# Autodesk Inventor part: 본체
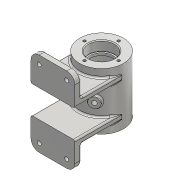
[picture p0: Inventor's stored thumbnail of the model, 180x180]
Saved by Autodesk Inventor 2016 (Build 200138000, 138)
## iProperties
Created: 2017-02
Part Number: 본체
Material: 알루미늄 6061
Document SubType Name: Modeling
Designer: H
Density: 2.7 g/cm^3
Appearance: 알루미늄 - 평지
Mass: 354.506 g
Surface Area: 423.347 cm^2
Volume: 131.299 cm^3
Author: H
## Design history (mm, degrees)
sketch "스케치1"
  geometry: L1 (0, 0)-(0, -48.036); L2 (0, 0)-(27, 0); L3 (27, 35)-(0, 35); L4 (0, 35)-(0, -35); L5 (0, -35)-(27, -35); L6 (27, -35)-(27, 35); L7 (0, -10)-(27, -10); L8 (32, -5)-(21.317, -5); L9 (21.317, -5)-(21.317, -10); L10 (21.317, -10)-(32, -10); L11 (32, -10)-(32, -5)
  constraints: 22 end point, 4 horizontal, 4 parallel, 4 point on line, 2 perpendicular, 1 vertical, 1 other
  dimensions: "d0" = 54 diameter of L6 L1; "d1" = 48.03642 distance of L1.start L1.end; "d2" = 27 distance of L1.start L2.end; "d4" = 70 distance of L5.end L3.start; "d5" = 5 distance of L10.end L8.start; "d6" = 10.68275 distance of L8.start L8.end; "d7" = 5 distance between parallel lines of L6 L11; "d109" = 25 distance between parallel lines of L5 L10
revolve "회전1" stored, may be unused: angle "d8" = 90 deg
revolve "회전2" stored, may be unused: angle "d9" = 90 deg
sketch "스케치2"
  geometry: L1 (-52, 52)-(-60, 52); L2 (-60, 52)-(-60, 17); L3 (-60, 17)-(-52, 17); L4 (-52, 17)-(-52, 52); L5 (0, 0)-(-22.662, 0); L6 (-52, 17)-(-2, 17); L7 (-2, 17)-(-2, 25); L8 (-2, 25)-(-52, 25); L9 (-52, 25)-(-52, 17)
  constraints: 18 end point, 4 parallel, 3 horizontal, 2 perpendicular
  dimensions: "d10" = 22.66207 distance of L5.start L5.end; "d11" = 52 distance between parallel lines of L5 L1; "d12" = 8 distance of L1.start L1.end; "d13" = 17 distance between parallel lines of L5 L3; "d14" = 60 distance from line of L5.start L2; "d15" = 50 distance of L7.end L8.end; "d16" = 8 distance of L6.end L7.end
extrude "돌출1" join sketch "스케치2" stored distance "d17" = 54; taper "d18" = 0 deg
sketch "스케치3"
  geometry: 2 further points
  constraints: 1 coincident
hole "구멍1" sketch "스케치3" at (0, 0) diameter "d19" = 32; stored, may be unused: countersink angle "d23" = 90 deg, drill point angle "d25" = 0 deg; dims "d20" = 6, "d21" = 4, "d22" = 2, "d24" = 12
sketch "스케치4"
  geometry: 2 further points
  constraints: 1 coincident
hole "구멍2" sketch "스케치4" at (0, 0) diameter "d26" = 28; stored, may be unused: countersink angle "d30" = 90 deg, drill point angle "d32" = 0 deg; dims "d27" = 6, "d28" = 4, "d29" = 2, "d31" = 3
sketch "스케치5"
  geometry: 2 further points
  constraints: 1 coincident
hole "구멍3" sketch "스케치5" at (0, 0) diameter "d33" = 44; stored, may be unused: countersink angle "d37" = 90 deg, drill point angle "d39" = 0 deg; dims "d34" = 6, "d35" = 4, "d36" = 2, "d38" = 40
sketch "스케치6"
  geometry: C1 r 5 at (0, 0) reference; 2 further points
  constraints: 1 coincident
hole "구멍4" sketch "스케치6" at (0, 0) diameter "d40" = 5.188; stored, may be unused: countersink angle "d44" = 90 deg, drill point angle "d46" = 0 deg; dims "d41" = 12, "d42" = 4, "d43" = 2, "d45" = 23.25
sketch "스케치8" dims "d47" = 9
  geometry: L1 (14.5, 14.402)-(10, 11.804); L2 (10, 11.804)-(5.5, 14.402); L3 (5.5, 14.402)-(5.5, 19.598); L4 (5.5, 19.598)-(10, 22.196); L5 (10, 22.196)-(14.5, 19.598); L6 (14.5, 19.598)-(14.5, 14.402); L7 (0, -8)-(0, 27) reference; 4 further points
  constraints: 12 end point, 1 coincident, 1 horizontal alignment, 1 midpoint, 1 parallel, 15 other
  dimensions: "d48" = 17 horizontal distance of point (10, 17) point (27, -25); "d49" = 42 vertical distance of point (27, -25) point (10, 17)
extrude "돌출2" cut sketch "스케치8" distance "d50" = 3; taper "d51" = 0 deg
sketch "스케치9"
  geometry: 2 further points
  dimensions: "d52" = 42 vertical distance of point (10, 17) point (27, -25); "d53" = 17 horizontal distance of point (27, -25) point (10, 17)
hole "구멍5" sketch "스케치9" at (10, 17) diameter "d54" = 5; stored, may be unused: countersink angle "d58" = 90 deg, drill point angle "d60" = 0 deg; dims "d55" = 12, "d56" = 4, "d57" = 2, "d59" = 23.25
sketch "스케치10"
  geometry: L1 (5, 32)-(-5, 32) reference; L2 (0, 0)-(0, 32); 1 further point
  constraints: 2 end point, 1 midpoint, 1 point on line
  dimensions: "d67" = 21 distance of L2.start point (0, 21)
hole "구멍6" sketch "스케치10" at (0, 21) diameter "d68" = 3.459; stored, may be unused: countersink angle "d72" = 90 deg, drill point angle "d74" = 118 deg; dims "d69" = 8, "d70" = 4, "d71" = 2, "d73" = 10
fillet "모깎기2" dims "d79" = 10
fillet "모깎기3" dims "d80" = 2
fillet "모깎기4" dims "d81" = 2
fillet "모깎기5" dims "d82" = 2
fillet "모깎기6" dims "d83" = 2
fillet "모깎기7" dims "d84" = 2
fillet "모깎기8" dims "d85" = 2
fillet "모깎기9" dims "d86" = 2
chamfer "모따기1" distance "d87" = 1; stored, may be unused: second distance "d88" = 2, angle "d89" = 45 deg
fillet "모깎기10" dims "d90" = 0.3
fillet "모깎기11" dims "d91" = 3
sketch "스케치11"
  geometry: L1 (0, 0)-(14.705, -22.644); L2 (0, 0)-(0, -27); L3 (12.458, -19.184)-(16.339, -25.16); L4 (16.339, -25.16)-(21.371, -21.892); L5 (21.371, -21.892)-(17.49, -15.916); L6 (17.49, -15.916)-(12.458, -19.184); A1 r 27 centre (0, 0) between (-23.276, -13.683) and (23.276, -13.683) reference; 1 further point
  constraints: 12 end point, 2 parallel, 2 point on circle, 2 point on line, 1 perpendicular
  dimensions: "d92" = 33 deg angle of L2 L1; "d93" = 30 distance from line of point (0, 0) L4; "d94" = 6 distance from line of L3 L4.end; "d95" = 5.97589 vertical distance of L4.end L5.end
revolve "회전3" sketch "스케치11" stored, may be unused: angle "d96" = 90 deg
sketch "스케치13"
  geometry: 2 further points
  constraints: 1 coincident
hole "구멍7" sketch "스케치13" at (0, 0) diameter "d97" = 5.188; stored, may be unused: countersink angle "d101" = 90 deg, drill point angle "d103" = 118 deg; dims "d98" = 17.5, "d99" = 4, "d100" = 2, "d102" = 17.5
fillet "모깎기12" dims "d104" = 2
node "작업 평면2"
sketch "스케치14"
  geometry: L1 (0, 57.5)-(0, -12.5) reference; L2 (54, -19.5)-(54, -4.5) reference; L3 (60, -19.5)-(54, -19.5) reference; L4 (60, 3.5)-(60, -19.5) reference; L5 (2, 3.5)-(60, 3.5) reference; L6 (2, -0.5)-(2, 3.5) reference; L7 (50, -0.5)-(2, -0.5) reference; L8 (50, 45.5)-(2, 45.5) reference; L9 (2, 41.5)-(2, 45.5) reference; L10 (2, 41.5)-(60, 41.5) reference; L11 (60, 64.5)-(60, 41.5) reference; L12 (60, 64.5)-(54, 64.5) reference; L13 (54, 64.5)-(54, 49.5) reference; L14 (-27, -12.5)-(27, -12.5) reference; L15 (27, 57.5)-(27, -12.5) reference; A1 r 4 centre (50, -4.5) between (50, -0.5) and (54, -4.5) reference; A2 r 4 centre (50, 49.5) between (54, 49.5) and (50, 45.5) reference; 2 further points
  constraints: 1 other
  dimensions: "d105" = 35 distance from line of L14 point (0, 22.5); "d106" = 27 distance from line of L15 point (0, 22.5)
feature "엠보싱1" sketch "스케치14" dims "d0" = 54, "d1" = 48.03642, "d2" = 27, "d4" = 70, "d5" = 5, "d6" = 10.68275, "d7" = 5, "d10" = 22.66207, "d11" = 52, "d12" = 8, "d13" = 17, "d14" = 60, "d15" = 50, "d16" = 8, "d107" = 0.5, "d108" = 0, "d109" = 25
node "솔리드1"
mirror "대칭1"
mirror "대칭2"
pattern_linear "직사각형 패턴1" dims "d63" = 34, "d66" = 84
pattern_circular "원형 패턴1" dims angle "d76" = 360 deg
mirror "대칭3"
node "절단 모서리 투영1"
